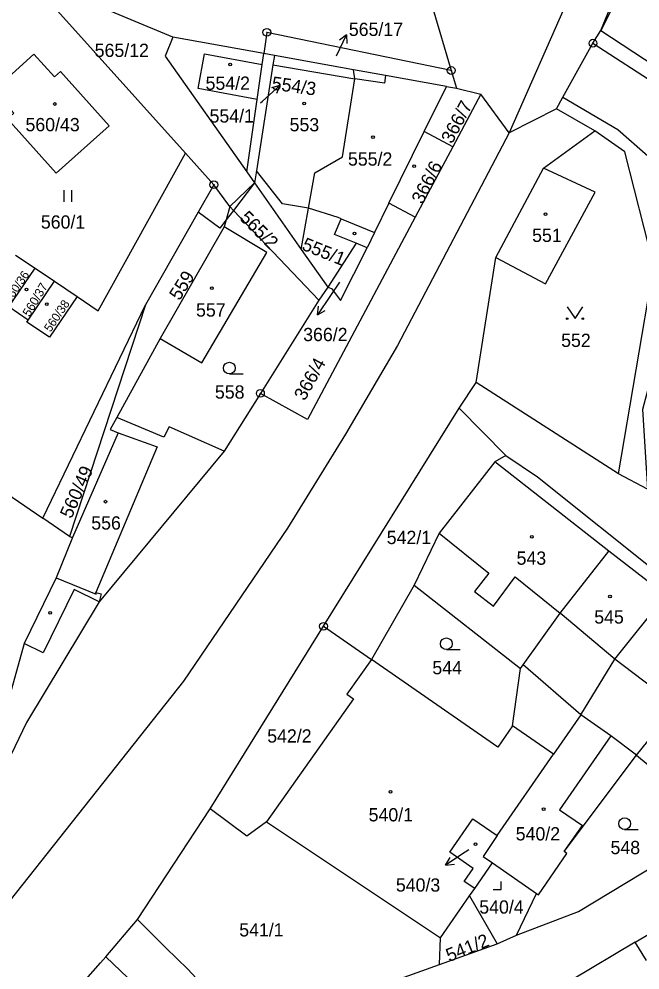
# Model space of a CAD drawing. Extents: x -776701 to -776081, y -974398 to -973771.
# Drawn here: x -776268.3 to -776188.7, y -974187.7 to -974065.8 of the extents above; entities that cross this region are included whole.
import ezdxf

# ---------------------------------------------------------------- set-up
doc = ezdxf.new("R2010")
doc.units = 0
for name, color, linetype in [('Hranice parcel', 7, 'Continuous'), ('Parcelní čísla', 7, 'Continuous'), ('Pop  PČ popisy', 7, 'Continuous'), ('Poz předměty', 7, 'Continuous'), ('Vnitřní kresba', 7, 'Continuous'), ('Značky bodu BP', 7, 'Continuous'), ('Značky budov', 7, 'Continuous'), ('Značky kultur', 7, 'Continuous')]:
    doc.layers.add(name, color=color, linetype=linetype)

msp = doc.modelspace()

# ---------------------------------------------------------------- linework, layer by layer
at = {"layer": 'Hranice parcel'}
for p, q in [((-776172.13, -974024.06), (-776193.76, -974067.27)), ((-776248.62, -974068.16), (-776267.37, -974060.3)), ((-776246.97, -974083.03), (-776267.37, -974060.3)), ((-776215.3, -974064.46), (-776212.94, -974072.41)), ((-776194.77, -974068.92), (-776193.76, -974067.27)), ((-776193.76, -974067.27), (-776186.79, -974071.85)), ((-776236.95, -974070.25), (-776248.62, -974068.16)), ((-776198.63, -974075.84), (-776194.77, -974068.92)), ((-776194.77, -974068.92), (-776186.22, -974074.45)), ((-776237.15, -974071.66), (-776236.95, -974070.25)), ((-776235.6, -974070.5), (-776236.95, -974070.25)), ((-776225.44, -974072.32), (-776235.6, -974070.5)), ((-776237.8, -974076.14), (-776237.15, -974071.66)), ((-776221.34, -974073.05), (-776225.44, -974072.32)), ((-776212.94, -974072.41), (-776212.26, -974074.69)), ((-776213.53, -974074.46), (-776221.34, -974073.05)), ((-776216.39, -974080.23), (-776213.53, -974074.46)), ((-776213.53, -974074.46), (-776212.26, -974074.69)), ((-776239.15, -974085.41), (-776237.8, -974076.14)), ((-776220.94, -974089.42), (-776216.39, -974080.23)), ((-776212.74, -974082.19), (-776216.39, -974080.23)), ((-776201.1, -974084.92), (-776194.55, -974080.16)), ((-776212.74, -974082.19), (-776217.54, -974091.22)), ((-776243.36, -974087.05), (-776246.97, -974083.03)), ((-776207.22, -974096.36), (-776201.1, -974084.92)), ((-776239.15, -974085.41), (-776238.14, -974086.83)), ((-776241.29, -974089.86), (-776243.36, -974087.05)), ((-776238.14, -974086.83), (-776240.84, -974090.34)), ((-776238.14, -974086.83), (-776232.15, -974095.34)), ((-776240.84, -974090.34), (-776241.29, -974089.86)), ((-776217.54, -974091.22), (-776220.94, -974089.42)), ((-776229.91, -974101.87), (-776240.84, -974090.34)), ((-776232.15, -974095.34), (-776231.21, -974090.06)), ((-776227.41, -974091.26), (-776231.21, -974090.06)), ((-776242.03, -974092.45), (-776250.25, -974106.78)), ((-776225.1, -974094.56), (-776228.73, -974100.18)), ((-776223.7, -974095.13), (-776225.1, -974094.56)), ((-776268.76, -974096.07), (-776266.27, -974097.75)), ((-776232.15, -974095.34), (-776228.73, -974100.18)), ((-776209.73, -974112.42), (-776207.22, -974096.36)), ((-776269.64, -974102.72), (-776266.27, -974097.75)), ((-776266.27, -974097.75), (-776263.79, -974099.43)), ((-776267.15, -974104.4), (-776263.79, -974099.43)), ((-776263.79, -974099.43), (-776260.89, -974101.39)), ((-776228.73, -974100.18), (-776229.91, -974101.87)), ((-776228.73, -974100.18), (-776228.3, -974100.37)), ((-776229.91, -974101.87), (-776237.39, -974113.79)), ((-776267.15, -974104.4), (-776269.64, -974102.72)), ((-776265.27, -974129.8), (-776252.11, -974102.44)), ((-776252.11, -974102.44), (-776261.84, -974132.15)), ((-776267.32, -974104.65), (-776267.15, -974104.4)), ((-776250.25, -974106.78), (-776255.8, -974116.9)), ((-776211.93, -974115.7), (-776209.73, -974112.42)), ((-776191.49, -974124.12), (-776209.73, -974112.42)), ((-776237.39, -974113.79), (-776242.05, -974121.22)), ((-776229.3, -974143.65), (-776211.93, -974115.7)), ((-776192.75, -974134.02), (-776207.36, -974122.58)), ((-776187.78, -974126.09), (-776191.49, -974124.12)), ((-776261.84, -974132.15), (-776265.27, -974129.8)), ((-776261.84, -974132.15), (-776261.46, -974132.25)), ((-776185.41, -974139.72), (-776192.75, -974134.02)), ((-776217.69, -974138.39), (-776223.14, -974147.9)), ((-776217.69, -974138.39), (-776204.05, -974149.05)), ((-776243.85, -974167.06), (-776229.3, -974143.65)), ((-776229.3, -974143.65), (-776223.14, -974147.9)), ((-776205.07, -974156.39), (-776204.05, -974149.05)), ((-776196.33, -974155), (-776199.82, -974160.03)), ((-776199.82, -974160.03), (-776205.07, -974156.39)), ((-776207.03, -974170.47), (-776199.82, -974160.03)), ((-776189.18, -974160.16), (-776178.4, -974169.17)), ((-776253.13, -974181.24), (-776243.85, -974167.06)), ((-776236.61, -974168.7), (-776214.31, -974183.56)), ((-776209.93, -974177.26), (-776207.65, -974173.97)), ((-776207.65, -974173.97), (-776202.01, -974177.89)), ((-776210.59, -974178.2), (-776209.93, -974177.26)), ((-776214.31, -974183.56), (-776210.59, -974178.2)), ((-776210.59, -974178.2), (-776207.03, -974184.36)), ((-776204.55, -974183.22), (-776202.01, -974177.89)), ((-776189.37, -974184.15), (-776182.59, -974180.14)), ((-776257.21, -974185.99), (-776253.13, -974181.24)), ((-776214.42, -974187), (-776214.31, -974183.56)), ((-776207.03, -974184.36), (-776204.55, -974183.22)), ((-776214.42, -974187), (-776207.03, -974184.36)), ((-776187.91, -974186.49), (-776189.37, -974184.15)), ((-776257.21, -974185.99), (-776252.4, -974190.58))]:
    msp.add_line(p, q, dxfattribs=at)
for points in [[(-776193.76, -974067.27), (-776174.47, -974020.28), (-776171.99, -974017.55)], [(-776212.94, -974072.41), (-776236.56, -974067.53), (-776236.95, -974070.25)], [(-776248.62, -974068.16), (-776249.58, -974070.59), (-776239.15, -974085.41)], [(-776266.42, -974070.32), (-776263.79, -974073.24), (-776263.01, -974072.55), (-776256.77, -974079.49), (-776263.55, -974085.59), (-776269.82, -974078.62), (-776268.99, -974077.88), (-776271.61, -974074.97), (-776266.42, -974070.32)], [(-776237.8, -974076.14), (-776245.37, -974074.74), (-776244.54, -974070.27), (-776237.15, -974071.66)], [(-776235.6, -974070.5), (-776235.78, -974071.68), (-776237.9, -974085.29), (-776238.14, -974086.83)], [(-776231.21, -974090.06), (-776230.4, -974085.52), (-776226.87, -974083.47), (-776225.3, -974073.49), (-776225.44, -974072.32)], [(-776212.26, -974074.69), (-776209.16, -974075.46), (-776212.74, -974082.19)], [(-776194.55, -974080.16), (-776199.45, -974077.31), (-776198.63, -974075.84)], [(-776198.63, -974075.84), (-776191.6, -974079.99), (-776185.25, -974085.51), (-776183.37, -974096.97), (-776188.41, -974115.88), (-776187.78, -974126.09)], [(-776191.49, -974124.12), (-776186.99, -974097.43), (-776190.67, -974082.84), (-776194.55, -974080.16)], [(-776260.89, -974101.39), (-776258.17, -974103.23), (-776246.97, -974083.03)], [(-776207.22, -974096.36), (-776200.86, -974099.76), (-776194.48, -974087.99), (-776201.1, -974084.92)], [(-776243.36, -974087.05), (-776245.36, -974090.57), (-776252.11, -974102.44)], [(-776241.29, -974089.86), (-776241.78, -974091.56), (-776242.03, -974092.45)], [(-776220.94, -974089.42), (-776222.79, -974093.16), (-776223.7, -974095.13)], [(-776217.54, -974091.22), (-776231.34, -974117.15), (-776237.39, -974113.79)], [(-776225.1, -974094.56), (-776227.89, -974093.42), (-776227.06, -974091.41), (-776227.41, -974091.26)], [(-776321.52, -974091.59), (-776295.28, -974109.27), (-776265.27, -974129.8)], [(-776250.25, -974106.78), (-776244.91, -974109.88), (-776236.57, -974095.73), (-776242.03, -974092.45)], [(-776228.3, -974100.37), (-776227.13, -974101.88), (-776223.7, -974095.13)], [(-776260.89, -974101.39), (-776264.42, -974106.61), (-776267.32, -974104.65)], [(-776211.93, -974115.7), (-776205.92, -974121.75), (-776207.36, -974122.58)], [(-776255.8, -974116.9), (-776256.64, -974118.44), (-776255.64, -974118.87), (-776261.46, -974132.25)], [(-776242.05, -974121.22), (-776249.07, -974118.09), (-776249.76, -974119.4), (-776255.8, -974116.9)], [(-776242.05, -974121.22), (-776258.05, -974140.53), (-776267.35, -974155.99), (-776274.82, -974171.4)], [(-776207.36, -974122.58), (-776214.5, -974131.7), (-776217.69, -974138.39)], [(-776261.46, -974132.25), (-776263.57, -974137.45), (-776267.68, -974145.84), (-776274.82, -974171.4)], [(-776204.05, -974149.05), (-776203.72, -974148.59), (-776198.98, -974141.97), (-776192.75, -974134.02)], [(-776196.33, -974155), (-776191.95, -974147.85), (-776185.41, -974139.72)], [(-776189.18, -974160.16), (-776184.09, -974153.89), (-776177.76, -974145.88)], [(-776223.14, -974147.9), (-776226.31, -974152.33), (-776225.45, -974152.94), (-776236.61, -974168.7)], [(-776205.07, -974156.39), (-776206.97, -974159.12), (-776223.14, -974147.9)], [(-776189.18, -974160.16), (-776192.48, -974157.7), (-776196.33, -974155)], [(-776202.01, -974177.89), (-776201.77, -974178.06), (-776198.1, -974172.76), (-776198.45, -974172.52), (-776189.18, -974160.16)], [(-776236.61, -974168.7), (-776239.12, -974170.56), (-776243.85, -974167.06)], [(-776209.93, -974177.26), (-776211.26, -974176.34), (-776210.11, -974174.67), (-776213.11, -974172.6), (-776210.15, -974168.31), (-776207.03, -974170.47)], [(-776204.55, -974183.22), (-776196.62, -974180.18), (-776178.4, -974169.17)], [(-776207.03, -974170.47), (-776208.86, -974173.13), (-776207.65, -974173.97)], [(-776253.13, -974181.24), (-776249.5, -974184.85), (-776246.7, -974187.6), (-776241.4, -974193.3), (-776237.63, -974197.45)], [(-776189.37, -974184.15), (-776197.53, -974188.99), (-776214.16, -974195.64)], [(-776259.77, -974188.9), (-776257.88, -974186.77), (-776257.21, -974185.99)], [(-776237.63, -974197.45), (-776226.37, -974191.27), (-776214.42, -974187)]]:
    msp.add_lwpolyline(points, dxfattribs=at)
at = {"layer": 'Pop  PČ popisy'}
for p, q in [((-776227.63, -974070.55), (-776226.36, -974067.83)), ((-776226.36, -974067.83), (-776227.24, -974068.53)), ((-776226.36, -974067.83), (-776226.33, -974068.95)), ((-776237.13, -974076.34), (-776234.9, -974074.33)), ((-776234.9, -974074.33), (-776235.98, -974074.63)), ((-776234.9, -974074.33), (-776235.31, -974075.37)), ((-776237.39, -974076.57), (-776237.13, -974076.34)), ((-776227.25, -974099.53), (-776228.41, -974101.24)), ((-776228.41, -974101.24), (-776230.09, -974103.73)), ((-776230.09, -974103.73), (-776229.94, -974102.62)), ((-776230.09, -974103.73), (-776229.11, -974103.18)), ((-776211.13, -974172.61), (-776213.65, -974174.24)), ((-776210.66, -974172.3), (-776211.13, -974172.61)), ((-776213.65, -974174.24), (-776213.08, -974173.28)), ((-776213.65, -974174.24), (-776212.53, -974174.12))]:
    msp.add_line(p, q, dxfattribs=at)
at = {"layer": 'Poz předměty'}
for p, q in [((-776193.46, -974053.03), (-776205.51, -974080.41)), ((-776205.51, -974080.41), (-776219.84, -974107.68)), ((-776219.84, -974107.68), (-776226.48, -974119.04)), ((-776226.48, -974119.04), (-776233.9, -974131.08)), ((-776233.9, -974131.08), (-776247.26, -974150.66)), ((-776247.26, -974150.66), (-776273.24, -974183.49))]:
    msp.add_line(p, q, dxfattribs=at)
at = {"layer": 'Vnitřní kresba'}
for p, q in [((-776235.78, -974071.68), (-776225.3, -974073.49)), ((-776221.49, -974074.04), (-776225.3, -974073.49)), ((-776221.34, -974073.05), (-776221.49, -974074.04)), ((-776205.51, -974080.41), (-776209.16, -974075.46)), ((-776199.45, -974077.31), (-776205.51, -974080.41)), ((-776234.55, -974089.5), (-776237.9, -974085.29)), ((-776241.29, -974089.86), (-776238.14, -974086.83)), ((-776231.21, -974090.06), (-776234.55, -974089.5)), ((-776242.58, -974092.61), (-776245.36, -974090.57)), ((-776240.84, -974090.34), (-776241.78, -974091.56)), ((-776241.78, -974091.56), (-776242.58, -974092.61)), ((-776227.06, -974091.41), (-776222.79, -974093.16)), ((-776255.64, -974118.87), (-776250.63, -974120.65)), ((-776250.63, -974120.65), (-776258.47, -974139.33)), ((-776205.92, -974121.75), (-776201.86, -974124.47)), ((-776201.86, -974124.47), (-776164.7, -974154.27)), ((-776214.5, -974131.7), (-776208.12, -974136.82)), ((-776263.57, -974137.45), (-776258.45, -974139.52)), ((-776208.12, -974136.82), (-776209.94, -974139.19)), ((-776207.5, -974141.08), (-776204.75, -974137.3)), ((-776204.75, -974137.3), (-776198.98, -974141.97)), ((-776261.28, -974138.95), (-776265.24, -974147.03)), ((-776258.05, -974140.53), (-776261.28, -974138.95)), ((-776258.47, -974139.33), (-776257.8, -974139.5)), ((-776258.45, -974139.52), (-776258.47, -974139.33)), ((-776257.8, -974139.5), (-776258.05, -974140.53)), ((-776209.94, -974139.19), (-776207.5, -974141.08)), ((-776191.95, -974147.85), (-776198.98, -974141.97)), ((-776265.24, -974147.03), (-776267.68, -974145.84)), ((-776184.09, -974153.89), (-776191.95, -974147.85)), ((-776196.33, -974155), (-776203.72, -974148.59)), ((-776192.48, -974157.7), (-776199.04, -974167.17)), ((-776199.04, -974167.17), (-776196.13, -974169.18)), ((-776198.45, -974172.52), (-776196.13, -974169.18))]:
    msp.add_line(p, q, dxfattribs=at)
at = {"layer": 'Značky bodu BP'}
for centre, radius in [((-776236.56, -974067.53), 0.5), ((-776236.56, -974067.53), 0.0303), ((-776194.77, -974068.92), 0.5), ((-776194.77, -974068.92), 0.0303), ((-776212.94, -974072.41), 0.5), ((-776212.94, -974072.41), 0.0303), ((-776243.36, -974087.05), 0.5), ((-776243.36, -974087.05), 0.0303), ((-776237.39, -974113.79), 0.5), ((-776237.39, -974113.79), 0.0303), ((-776229.3, -974143.65), 0.5), ((-776229.3, -974143.65), 0.0303)]:
    msp.add_circle(centre, radius, dxfattribs=at)
at = {"layer": 'Značky budov'}
for centre in [(-776241.28, -974071.65), (-776263.74, -974076.71), (-776231.77, -974076.63), (-776222.96, -974080.96), (-776217.67, -974084.66), (-776200.86, -974090.82), (-776225.32, -974093.3), (-776267.38, -974100.49), (-776243.63, -974100.31), (-776264.78, -974102.35), (-776257.26, -974127.67), (-776202.61, -974132.19), (-776192.59, -974139.83), (-776264.35, -974141.91), (-776220.73, -974164.87), (-776201.09, -974167.1), (-776209.84, -974171.56)]:
    msp.add_circle(centre, 0.175, dxfattribs=at)
at = {"layer": 'Značky kultur'}
for p, q in [((-776262.56, -974089.25), (-776262.56, -974087.75)), ((-776261.56, -974089.25), (-776261.56, -974087.75)), ((-776241.37, -974111.31), (-776239.62, -974111.31)), ((-776213.56, -974146.64), (-776211.81, -974146.64)), ((-776190.71, -974169.69), (-776188.96, -974169.69)), ((-776206.54, -974177.37), (-776206.54, -974176.37)), ((-776207.54, -974177.37), (-776206.54, -974177.37))]:
    msp.add_line(p, q, dxfattribs=at)
msp.add_lwpolyline([(-776198.07, -974102.71), (-776197.07, -974104.21), (-776196.07, -974102.71)], dxfattribs=at)
for centre, radius in [((-776198.07, -974104.21), 0.1), ((-776196.07, -974104.21), 0.1), ((-776241.37, -974110.56), 0.75), ((-776213.56, -974145.89), 0.75), ((-776190.71, -974168.94), 0.75)]:
    msp.add_circle(centre, radius, dxfattribs=at)

# ---------------------------------------------------------------- texts
at = {"layer": 'Parcelní čísla'}
for s, p in [('565/17', (-776226.06, -974067.99)), ('565/12', (-776258.63, -974070.68)), ('554/2', (-776244.42, -974074.89)), ('554/1', (-776243.91, -974079.09)), ('560/43', (-776267.5, -974080.2)), ('553', (-776233.65, -974080.21)), ('555/2', (-776226.17, -974084.61)), ('560/1', (-776265.53, -974092.68)), ('551', (-776202.57, -974094.39)), ('557', (-776245.64, -974103.96)), ('366/2', (-776231.91, -974107.1)), ('552', (-776198.85, -974107.85)), ('558', (-776243.22, -974114.47)), ('556', (-776259.07, -974131.25)), ('542/1', (-776221.2, -974133.11)), ('543', (-776204.56, -974135.76)), ('545', (-776194.61, -974143.3)), ('544', (-776215.35, -974149.8)), ('542/2', (-776236.52, -974158.55)), ('540/1', (-776223.52, -974168.65)), ('540/2', (-776204.67, -974171.09)), ('548', (-776192.52, -974172.85)), ('540/3', (-776220.03, -974177.65)), ('540/4', (-776209.34, -974180.47)), ('541/1', (-776240.1, -974183.4))]:
    msp.add_text(s, height=1.7, dxfattribs=at).set_placement(p)
for s, height, rotation, p in [('554/3', 1.7, 352, (-776236.02, -974074.84)), ('366/7', 1.7, 62, (-776212.83, -974081.9)), ('366/6', 1.7, 63, (-776216.6, -974089.65)), ('565/2', 1.7, 315, (-776240.16, -974091.43)), ('555/1', 1.7, 338, (-776232.2, -974095.34)), ('560/36', 1.1, 56, (-776269.47, -974102.3)), ('559', 1.7, 58, (-776247.76, -974102)), ('560/37', 1.139, 59, (-776266.98, -974104.07)), ('560/38', 1.1, 56, (-776264.29, -974106.02)), ('366/4', 1.7, 61, (-776231.7, -974114.84)), ('560/49', 1.7, 66, (-776261.61, -974129.94)), ('541/2', 1.7, 22, (-776213.19, -974186.69))]:
    msp.add_text(s, height=height, rotation=rotation, dxfattribs=at).set_placement(p)

doc.saveas('drawing.dxf')
